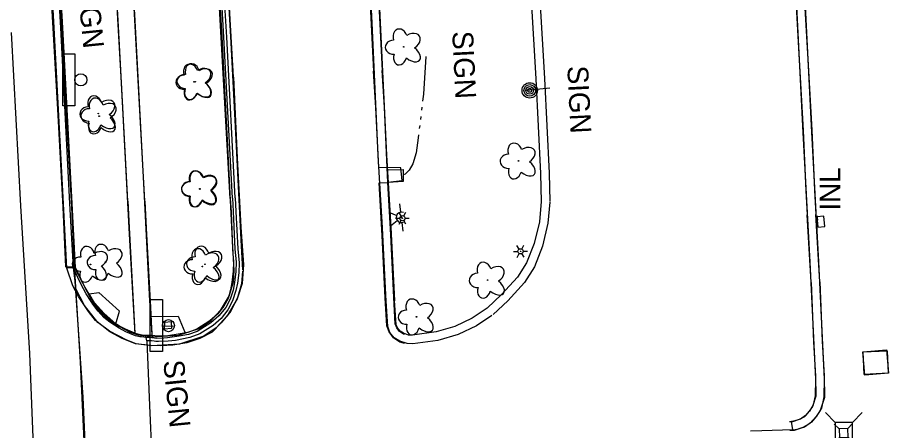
# Model space of a CAD drawing. Extents: x 588843 to 2552415, y 180129 to 269402.
# Drawn here: x 594760.9 to 595012.6, y 184586.7 to 184706 of the extents above; entities that cross this region are included whole.
import ezdxf

# ---------------------------------------------------------------- set-up
doc = ezdxf.new("R2010")
doc.units = 0
for name, color, linetype in [('Default', 7, 'Continuous'), ('E_BLD', 7, 'Continuous'), ('E_DWY', 7, 'Continuous'), ('E_LAND_Vegetation', 7, 'Continuous'), ('E_LTG', 7, 'Continuous'), ('E_MISCPROP', 7, 'Continuous'), ('E_MISCPROP_Planter', 7, 'Continuous'), ('E_PATH_Sidewalk', 7, 'Continuous'), ('E_RDWY', 7, 'Continuous'), ('E_RDWY_AsphConc', 7, 'Continuous'), ('E_RDWY_C_and_G', 7, 'Continuous'), ('E_RDWY_PavtEdge', 7, 'Continuous'), ('E_SGN', 7, 'Continuous'), ('E_SGN_Text', 7, 'Continuous'), ('E_UTL_AG_Bold', 7, 'Continuous'), ('E_WTR_P', 7, 'Continuous'), ('Level 15', 7, 'Continuous'), ('Level 17', 7, 'Continuous'), ('Level 21', 7, 'Continuous')]:
    doc.layers.add(name, color=color, linetype=linetype)

# ---------------------------------------------------------------- blocks, each defined once
blk = doc.blocks.new('SGN_1')
at = {"layer": 'Default'}
blk.add_lwpolyline([(-3.5, -15), (-10.5, -15), (-10.5, 15), (-3.5, 15)], close=True, dxfattribs=at)
blk.add_circle((0, 0), 3.5, dxfattribs=at)
blk = doc.blocks.new('DTRE_1_1')
at = {"layer": 'Default'}
blk.add_circle((-0.18, 0), 0.183, dxfattribs=at)
for centre, major_axis, ratio in [((-1.87, 5.32), (1.36, -4.98), 0.782863), ((4.06, 2.74), (-5.27, -2.93), 0.691916), ((-5.87, 0.15), (4.93, -0.12), 0.832022), ((-2.49, -5.24), (1.8, 4.86), 0.716896), ((3.54, -3.71), (-5.01, 4.58), 0.560249)]:
    blk.add_ellipse(centre, major_axis=major_axis, ratio=ratio, start_param=1.570796, end_param=4.712389, dxfattribs=at)
blk = doc.blocks.new('PED_3')
at = {"layer": 'E_UTL_AG_Bold'}
for p, q in [((-8.2, 8.2), (-17.5, 17.5)), ((8.2, 8.2), (17.5, 17.5)), ((-8.2, -8.2), (-17.5, -17.5)), ((8.2, -8.2), (17.5, -17.5))]:
    blk.add_line(p, q, dxfattribs=at)
blk.add_lwpolyline([(-8.2, -8.2), (8.2, -8.2), (8.2, 8.2), (-8.2, 8.2)], close=True, dxfattribs=at)
blk = doc.blocks.new('LPOL_4')
at = {"layer": 'E_LTG'}
for p, q in [((-13.1, 0), (-4.9, 0)), ((-2.5, 4.3), (-6.6, 11.4)), ((2.5, 4.3), (6.6, 11.4)), ((4.9, 0), (13.1, 0)), ((-6.6, -11.4), (-2.5, -4.3)), ((6.6, -11.4), (2.5, -4.3))]:
    blk.add_line(p, q, dxfattribs=at)
for radius in [4.92, 4.92, 4.92, 0.41]:
    blk.add_circle((0, 0), radius, dxfattribs=at)
blk = doc.blocks.new('SIGN_3')
at = {"layer": 'E_SGN'}
blk.add_text('SIGN', height=39.37, dxfattribs=at).set_placement((-56.1, -19.7))
blk = doc.blocks.new('POLE_3')
at = {"layer": 'E_MISCPROP'}
for radius in [14.6, 11, 7.32, 3.66]:
    blk.add_circle((0, 0), radius, dxfattribs=at)
blk = doc.blocks.new('DTRE_4')
at = {"layer": 'E_LAND_Vegetation'}
blk.add_circle((-0.6, 0), 0.601, dxfattribs=at)
for centre, major_axis, ratio in [((-6.1, 17.5), (4.5, -16.3), 0.782863), ((13.3, 9), (-17.3, -9.6), 0.691916), ((-19.3, 0.5), (16.2, -0.4), 0.832022), ((-8.2, -17.2), (5.9, 15.9), 0.716896), ((11.6, -12.2), (-16.4, 15), 0.560249)]:
    blk.add_ellipse(centre, major_axis=major_axis, ratio=ratio, start_param=1.570796, end_param=4.712389, dxfattribs=at)

msp = doc.modelspace()

# ---------------------------------------------------------------- linework, layer by layer
at = {"layer": 'E_BLD'}
msp.add_lwpolyline([(595005.22, 184609.41), (595012.05, 184610.01), (595012.65, 184603.26), (595005.81, 184602.66)], close=True, dxfattribs=at)
at = {"layer": 'E_DWY'}
for points in [[(594791.51, 184779.58), (594797.65, 184779.85), (594800.87, 184779.39), (594805.25, 184778.25), (594808.67, 184776.58), (594811.56, 184774.69), (594813.89, 184772.2), (594816.89, 184767.41), (594818.56, 184762.99), (594819.34, 184759.34), (594819.97, 184746.98), (594821.08, 184725.47), (594822.5, 184700.4)], [(594823.35, 184688.72), (594822.34, 184707.09), (594821.51, 184721.44), (594820.6, 184737.77), (594819.82, 184751.76), (594819.02, 184762.29), (594817.89, 184766.14), (594816.04, 184769.5), (594814.36, 184771.83), (594812.01, 184774.62), (594809.49, 184776.51), (594807.01, 184777.85), (594804.36, 184779.07), (594801.57, 184779.74), (594799, 184780.2), (594796.53, 184780.25), (594791.54, 184780.11)], [(594867.43, 184624.04), (594866.42, 184645.27), (594865.12, 184666.12), (594863.38, 184704.42), (594861.58, 184740.36), (594860.43, 184765.62), (594859.18, 184779.06)], [(594860.4, 184779.16), (594861.52, 184779.15), (594861.86, 184779.18), (594862.1, 184778.9), (594862.39, 184770.36), (594863.5, 184745.87), (594864.98, 184717.52), (594866.34, 184690.62)], [(594869.93, 184624.16), (594868.92, 184645.4), (594867.62, 184666.25), (594865.87, 184704.54), (594864.08, 184740.48), (594862.93, 184765.79), (594861.65, 184779.57)], [(594791.62, 184777.08), (594797.53, 184777.34), (594800.38, 184776.93), (594804.38, 184775.89), (594807.44, 184774.4), (594809.94, 184772.76), (594811.9, 184770.67), (594814.64, 184766.3), (594816.15, 184762.28), (594816.85, 184759.01), (594817.47, 184746.85), (594818.58, 184725.34), (594820.01, 184700.26)], [(594859.89, 184770.26), (594861.01, 184745.75), (594862.48, 184717.39), (594863.84, 184690.49)], [(594909.4, 184711.15), (594910.76, 184688.21), (594912.06, 184660.91), (594912.29, 184652.75)], [(594911.89, 184711.29), (594913.26, 184688.34), (594914.56, 184661), (594914.78, 184652.82)], [(594985.94, 184711.17), (594987.84, 184672.73), (594989.92, 184635.28), (594991.5, 184601.52), (594991.47, 184596.74), (594990.88, 184594.12), (594989.82, 184592.32), (594988.34, 184590.7), (594986.83, 184589.87), (594984.9, 184589.22), (594984, 184589.19)], [(594988.43, 184711.29), (594990.34, 184672.86), (594992.42, 184635.4), (594994, 184601.57), (594993.97, 184596.46), (594993.24, 184593.19), (594991.84, 184590.82), (594989.91, 184588.71), (594987.84, 184587.57), (594985.35, 184586.74), (594984.11, 184586.69)], [(594820, 184700.38), (594821.46, 184672.4), (594823.08, 184639.78), (594823.47, 184632.92)], [(594822.5, 184700.51), (594823.95, 184672.53), (594825.57, 184639.92), (594825.96, 184633.06)], [(594865.31, 184662.52), (594864.45, 184679.93), (594863.84, 184690.49)], [(594867.8, 184662.64), (594866.95, 184680.07), (594866.34, 184690.62)], [(594823.35, 184688.72), (594824.43, 184665.41), (594825.5, 184645.45), (594826.2, 184634.6), (594825.88, 184629.16), (594824.62, 184625.26), (594822.61, 184621.18), (594819.74, 184617.79), (594817.17, 184615.12), (594813.67, 184613.24), (594809.86, 184612.06), (594805.78, 184611.37), (594802.31, 184611.16), (594799.42, 184611.26), (594795.05, 184611.7), (594791.14, 184613.24), (594787.65, 184615.21), (594783.48, 184618.49), (594781.43, 184621.03), (594778.6, 184625.44), (594776.95, 184628.49), (594775.2, 184633.55)], [(594865.46, 184658.21), (594867.95, 184658.36), (594867.8, 184662.64), (594865.31, 184662.52)], [(594872.79, 184611.81), (594871.42, 184612.23), (594869.55, 184613.45), (594868.37, 184615.19), (594867.63, 184616.94), (594867.18, 184625.01), (594866.35, 184643.06), (594865.46, 184658.21)], [(594872.77, 184614.43), (594872.49, 184614.52), (594871.34, 184615.27), (594870.57, 184616.39), (594870.1, 184617.51), (594869.68, 184625.14), (594868.85, 184643.19), (594867.95, 184658.36)], [(594912.28, 184652.87), (594911.76, 184646.97), (594910.28, 184640.73), (594908.06, 184635.12), (594905.43, 184630.96), (594900.82, 184625.93), (594896.63, 184622.01)], [(594914.77, 184652.65), (594914.23, 184646.57), (594912.67, 184639.98), (594910.3, 184633.99), (594907.43, 184629.44), (594902.6, 184624.17), (594898.34, 184620.19)], [(594823.47, 184632.92), (594823.21, 184629.51), (594822.13, 184625.72), (594819.54, 184621.34), (594816.71, 184618.26), (594813.66, 184616.17), (594807.33, 184614.09), (594799.74, 184613.7), (594795.79, 184614.21), (594793.58, 184615.05), (594788.86, 184617.53), (594785.9, 184619.71), (594782.37, 184624.2), (594777.31, 184634.09)], [(594825.96, 184632.73), (594825.68, 184629.07), (594824.44, 184624.73), (594821.56, 184619.85), (594818.36, 184616.36), (594814.78, 184613.9), (594807.79, 184611.61), (594799.64, 184611.19), (594795.18, 184611.77), (594792.55, 184612.77), (594787.53, 184615.4), (594784.14, 184617.9), (594780.26, 184622.84), (594777.72, 184627.81)], [(594898.01, 184619.93), (594893.56, 184616.97), (594888.24, 184614.44), (594882.39, 184612.73), (594875.21, 184611.76), (594873.49, 184611.78), (594871.37, 184612.53), (594869.82, 184613.47), (594868.54, 184615.05), (594867.91, 184616.7), (594867.43, 184624.07)], [(594896.63, 184622.01), (594892.33, 184619.15), (594887.35, 184616.78), (594881.87, 184615.18), (594875.06, 184614.26), (594873.94, 184614.27), (594872.45, 184614.8), (594871.49, 184615.38), (594870.73, 184616.32), (594870.38, 184617.24), (594869.92, 184624.23)]]:
    msp.add_lwpolyline(points, dxfattribs=at)
at = {"layer": 'E_LTG'}
for p, q in [((594868.21, 184649.79), (594870.51, 184648.81)), ((594871.71, 184649.72), (594871.41, 184652.2)), ((594868.69, 184645.82), (594870.69, 184647.33)), ((594872.37, 184644.26), (594872.07, 184646.74))]:
    msp.add_line(p, q, dxfattribs=at)
msp.add_circle((594871.89, 184648.23), 0.125, dxfattribs=at)
msp.add_arc((594871.89, 184648.23), 1.5, 68.7097, 292.3879, dxfattribs=at)
at = {"layer": 'E_MISCPROP_Planter'}
msp.add_lwpolyline([(594799.67, 184619.64), (594807.33, 184619.74), (594809.32, 184615.14)], dxfattribs=at)
at = {"layer": 'E_PATH_Sidewalk'}
for points in [[(594797.74, 184652.91), (594794.94, 184703.55), (594793.4, 184731.28), (594796.14, 184735.68), (594795.81, 184750.1), (594792.41, 184753.56), (594791.37, 184777.06), (594786.45, 184776.63)], [(594792.8, 184652.96), (594790.08, 184703.35), (594788.47, 184732.25), (594791.3, 184737.24), (594790.98, 184748.34), (594787.5, 184752.99), (594786.45, 184776.63)], [(594791.25, 184776.72), (594786.56, 184776.42), (594787.4, 184753.25), (594787.66, 184752.35), (594790.93, 184748.04), (594791.31, 184736.87), (594788.45, 184731.85), (594788.53, 184729.27), (594790.77, 184688.8), (594793.22, 184643.35), (594794.8, 184614.59)], [(594791.18, 184776.71), (594792.42, 184753.24), (594795.34, 184750.57), (594795.67, 184749.96), (594796.29, 184736.37), (594796.13, 184735.8), (594793.18, 184731.22), (594794.7, 184706.82), (594797.33, 184658.05), (594799.1, 184624.16), (594799.83, 184613.6)], [(594792.8, 184652.96), (594793.24, 184645.36), (594794.5, 184622.01), (594794.8, 184614.83)], [(594797.74, 184652.91), (594798.07, 184645.09), (594799.35, 184622.2), (594799.72, 184614.11)]]:
    msp.add_lwpolyline(points, dxfattribs=at)
at = {"layer": 'E_RDWY'}
for points in [[(594867.95, 184658.46), (594872.12, 184658.89), (594871.75, 184662.52), (594867.81, 184662.6)], [(594867.78, 184661.98), (594872.36, 184662.06), (594872.41, 184658.61), (594868.01, 184658.33)], [(594777.4, 184632.83), (594779.06, 184606.45), (594780.67, 184571.28), (594781.19, 184555.56), (594782.21, 184523.33), (594782.74, 184513.75), (594784.36, 184495.78), (594784.28, 184494.37)]]:
    msp.add_lwpolyline(points, dxfattribs=at)
at = {"layer": 'E_RDWY_AsphConc'}
for points in [[(594781.64, 184555.76), (594781.37, 184563.82), (594779.87, 184596.3), (594777.6, 184629.78), (594777.08, 184633.63)], [(594789.34, 184617.54), (594785.96, 184620.52), (594783.2, 184623.61), (594781.65, 184626.13), (594784.42, 184626.52), (594790.45, 184621.12)], [(594789.34, 184617.54), (594790.45, 184621.12)], [(594798.34, 184612.59), (594799.04, 184593.94), (594799.76, 184578.72), (594799.79, 184578.23)]]:
    msp.add_lwpolyline(points, dxfattribs=at)
msp.add_lwpolyline([(594805.42, 184616.19), (594803.46, 184616), (594803.48, 184618.03), (594805.36, 184618.17)], close=True, dxfattribs=at)
at = {"layer": 'E_RDWY_C_and_G'}
for points in [[(594764.27, 184831.13), (594766.46, 184789.1), (594769.36, 184734.71), (594772.55, 184677.72)], [(594766.76, 184831.26), (594768.96, 184789.23), (594771.86, 184734.85), (594775.04, 184677.86)], [(594777.08, 184633.63), (594775.2, 184633.55), (594774.21, 184652.19), (594771.49, 184702.97), (594768.71, 184753.45), (594765.95, 184803.81)], [(594778.76, 184630.05), (594777.08, 184633.63), (594776.1, 184652.26), (594773.41, 184702.94), (594770.48, 184753.24), (594767.8, 184803.8)], [(594779.34, 184630.27), (594777.65, 184633.73), (594776.77, 184652.29), (594773.99, 184703.02), (594771.16, 184753.32), (594768.38, 184803.92)], [(594822.37, 184653.72), (594819.8, 184700.18), (594818.89, 184715.65)], [(594823.06, 184653.8), (594820.55, 184700.24), (594819.67, 184715.66)], [(594823.84, 184653.88), (594821.39, 184700.32), (594820.5, 184715.79)], [(594772.55, 184677.72), (594774, 184651.16), (594774.81, 184633.97), (594777.31, 184634.09)], [(594775.04, 184677.86), (594776.5, 184651.29), (594777.31, 184634.09)], [(594823.06, 184653.8), (594823.24, 184649.94), (594823.76, 184639.07), (594824.13, 184635.38), (594824.13, 184635.38), (594824.07, 184632.64), (594824.07, 184632.64), (594823.68, 184629.43), (594823.68, 184629.43), (594823.25, 184627.18), (594823.25, 184627.18), (594822.41, 184624.61), (594821.09, 184622.25), (594821.09, 184622.25), (594819.13, 184619.86), (594816.8, 184617.83), (594816.8, 184617.83), (594812.83, 184615.34), (594812.83, 184615.34), (594810.37, 184614.44), (594810.37, 184614.44), (594807.68, 184613.93), (594807.68, 184613.93), (594804.27, 184613.45), (594804.27, 184613.45), (594803.18, 184613.35), (594803.18, 184613.35), (594801.18, 184613.28), (594801.18, 184613.28), (594799.75, 184613.51), (594798.16, 184613.59), (594796.76, 184613.73), (594796.31, 184613.78), (594795.05, 184614.05), (594795.05, 184614.05), (594794.56, 184614.21), (594794.56, 184614.21), (594792.21, 184615.22), (594792.21, 184615.22), (594790.27, 184616.22), (594790.27, 184616.22), (594787.59, 184617.94), (594787.59, 184617.94), (594785.92, 184619.34), (594785.92, 184619.34), (594784.23, 184621.19), (594784.23, 184621.19), (594782.7, 184623.22), (594782.7, 184623.22), (594782.21, 184623.97), (594782.21, 184623.97), (594780.77, 184626.21), (594780.77, 184626.21), (594779.96, 184627.62), (594779.96, 184627.62), (594778.76, 184630.05), (594778.76, 184630.05)], [(594822.37, 184653.72), (594822.67, 184649.81), (594823.1, 184639.09), (594823.38, 184635.41), (594823.38, 184635.41), (594823.29, 184632.67), (594823.29, 184632.67), (594822.91, 184629.46), (594822.91, 184629.46), (594822.53, 184627.29), (594822.53, 184627.29), (594821.77, 184624.85), (594820.55, 184622.59), (594820.55, 184622.59), (594818.73, 184620.31), (594816.55, 184618.37), (594816.55, 184618.37), (594812.71, 184615.95), (594812.71, 184615.95), (594810.13, 184615.01), (594810.13, 184615.01), (594807.4, 184614.49), (594807.4, 184614.49), (594804.34, 184614.06), (594804.34, 184614.06), (594803.38, 184613.99), (594803.38, 184613.99), (594801.58, 184613.95), (594801.58, 184613.95), (594799.72, 184614.11), (594798.2, 184614.15), (594796.97, 184614.19), (594796.52, 184614.34), (594795.3, 184614.66), (594795.3, 184614.66), (594794.8, 184614.83), (594794.8, 184614.83), (594792.12, 184615.96), (594792.12, 184615.96), (594790.43, 184616.82), (594790.43, 184616.82), (594788.38, 184618.13), (594788.38, 184618.13), (594786.38, 184619.78), (594786.38, 184619.78), (594784.27, 184621.95), (594784.27, 184621.95), (594783.09, 184623.55), (594783.09, 184623.55), (594782.72, 184624.15), (594782.72, 184624.15), (594781.33, 184626.52), (594781.33, 184626.52), (594780.53, 184627.96), (594780.53, 184627.96), (594779.34, 184630.27), (594779.34, 184630.27)], [(594823.84, 184653.88), (594824.03, 184649.92), (594824.65, 184639.12), (594825.01, 184635.15), (594825.01, 184635.15), (594824.89, 184632.19), (594824.89, 184632.19), (594824.47, 184629.29), (594824.47, 184629.29), (594824.04, 184627.09), (594824.04, 184627.09), (594823.1, 184624.19), (594821.67, 184621.51), (594821.67, 184621.51), (594819.78, 184619.09), (594817.49, 184617.05), (594817.49, 184617.05), (594813.61, 184614.61), (594813.61, 184614.61), (594810.72, 184613.55), (594810.72, 184613.55), (594806.6, 184612.72), (594806.6, 184612.72), (594804.43, 184612.48), (594804.43, 184612.48), (594801.65, 184612.38), (594801.65, 184612.38), (594800.93, 184612.41), (594800.93, 184612.41), (594800.41, 184612.46), (594800.41, 184612.46), (594799.62, 184612.56), (594799.62, 184612.56), (594799.16, 184612.59), (594799.16, 184612.59), (594798.34, 184612.59), (594798.34, 184612.59), (594798.16, 184613.59)]]:
    msp.add_lwpolyline(points, dxfattribs=at)
at = {"layer": 'E_RDWY_PavtEdge'}
msp.add_lwpolyline([(594769.3, 184449.63), (594768.81, 184476.19), (594768.17, 184495.11), (594766.41, 184560.33), (594764.46, 184608.96), (594761.88, 184651.59), (594759.18, 184701.67)], dxfattribs=at)
at = {"layer": 'E_SGN'}
for p, q in [((594908.04, 184684.97), (594914.8, 184685.69)), ((594803.1, 184616.95), (594805.94, 184616.86))]:
    msp.add_line(p, q, dxfattribs=at)
at = {"layer": 'E_WTR_P'}
for points in [[(594878.9, 184694.71), (594878.23, 184683.78), (594878, 184681.83)], [(594877.79, 184680.06), (594877.68, 184679.18)], [(594877.47, 184677.41), (594877.36, 184676.52)], [(594877.15, 184674.76), (594877.04, 184673.87)], [(594876.82, 184672.11), (594876.71, 184671.25), (594876.1, 184666.9), (594875.19, 184663.72), (594874.14, 184661.84), (594873, 184660.68), (594872.45, 184660.55)]]:
    msp.add_lwpolyline(points, dxfattribs=at)
at = {"layer": 'Level 15'}
msp.add_lwpolyline([(594992.25, 184645.39), (594994.23, 184645.61), (594993.9, 184648.59), (594991.91, 184648.37), (594992.25, 184645.39)], dxfattribs=at)
at = {"layer": 'Level 17'}
for points in [[(594985.81, 184711.02), (594986.83, 184693.76), (594987.94, 184673.3), (594988.74, 184655.93), (594989.15, 184649.05)], [(594988.36, 184710.27), (594989.33, 184693.9), (594990.43, 184673.43), (594991.24, 184656.06), (594991.66, 184649.05)], [(594990.27, 184629.5), (594989.15, 184649.02)], [(594992.77, 184629.63), (594991.65, 184649.09)], [(594991.66, 184649.05), (594991.66, 184649.02)], [(594992.02, 184648.66), (594992.05, 184648.18), (594992.09, 184647.4), (594991.75, 184647.38)], [(594992.77, 184629.63), (594993.42, 184612.48), (594994.07, 184602.47), (594994.13, 184596.25), (594992.91, 184592.46), (594991.7, 184590.79), (594990.34, 184589.16), (594988.31, 184587.7), (594985.81, 184586.94)], [(594990.27, 184629.48), (594990.92, 184612.35), (594991.57, 184602.38), (594991.63, 184596.63), (594990.66, 184593.61), (594989.73, 184592.32), (594988.63, 184591.01), (594987.19, 184589.97), (594985.17, 184589.36), (594984.64, 184589.29)], [(594984.94, 184586.91), (594976.02, 184586.59), (594972.73, 184586.48)], [(594984.94, 184586.91), (594984.64, 184589.29)], [(594985.81, 184586.94), (594985.7, 184586.9), (594984.96, 184586.81), (594984.94, 184586.91)]]:
    msp.add_lwpolyline(points, dxfattribs=at)
at = {"layer": 'Level 21'}
for p, q in [((594997.22, 184589.05), (594994.39, 184591.88)), ((595002.22, 184589.05), (595005.05, 184591.88))]:
    msp.add_line(p, q, dxfattribs=at)
msp.add_lwpolyline([(595005.6, 184602.86), (595005.27, 184609.39), (595012.21, 184609.74), (595012.54, 184603.22), (595005.6, 184602.86)], dxfattribs=at)
msp.add_lwpolyline([(594997.22, 184584.05), (595002.22, 184584.05), (595002.22, 184589.05), (594997.22, 184589.05)], close=True, dxfattribs=at)

# ---------------------------------------------------------------- block references
at = {"layer": 'E_LAND_Vegetation', "xscale": 0.15240030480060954, "yscale": 0.15240030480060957, "rotation": 3.4338469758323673}
for p in [(594872.63, 184697.5), (594812.09, 184687.38), (594784.38, 184678.21), (594905.8, 184664.56), (594813.7, 184656.51), (594786.45, 184635.33), (594814.45, 184634.08), (594896.88, 184630.15), (594876.33, 184619.54)]:
    msp.add_blockref('DTRE_4', p, dxfattribs=at)
at = {"layer": 'E_LAND_Vegetation', "xscale": 0.5, "yscale": 0.5}
for p in [(594812.41, 184687.41), (594784.63, 184677.47), (594813.71, 184656.43), (594782.12, 184634.66), (594815.18, 184634.71)]:
    msp.add_blockref('DTRE_1_1', p, dxfattribs=at)
at = {"layer": 'E_LTG', "xscale": 0.15240030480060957, "yscale": 0.15240030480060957, "rotation": 0.8014450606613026}
for p in [(594872.16, 184648), (594906.29, 184638.44)]:
    msp.add_blockref('LPOL_4', p, dxfattribs=at)
at = {"layer": 'E_MISCPROP', "xscale": 0.15240030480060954, "yscale": 0.15240030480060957, "rotation": 3.4338469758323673}
msp.add_blockref('POLE_3', (594908.95, 184684.91), dxfattribs=at)
at = {"layer": 'E_SGN', "xscale": 0.5, "yscale": 0.5}
for p in [(594779.25, 184687.98), (594804.54, 184616.99)]:
    msp.add_blockref('SGN_1', p, dxfattribs=at)
at = {"layer": 'E_SGN_Text', "xscale": 0.15240030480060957}
for p, yscale, rotation in [((594781.91, 184708.09), 0.1524003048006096, -84.31519139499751), ((594889.97, 184693.52), 0.15240030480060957, -87.12209734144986), ((594923.22, 184683.52), 0.15240030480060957, -87.12209734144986), ((594806.87, 184598.57), 0.1524003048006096, -84.31519139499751)]:
    msp.add_blockref('SIGN_3', p, dxfattribs=dict(at, yscale=yscale, rotation=rotation))
at = {"layer": 'E_UTL_AG_Bold', "xscale": 0.1524003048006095, "yscale": 0.15240030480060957, "rotation": 2.3276622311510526}
msp.add_blockref('PED_3', (594999.69, 184585.97), dxfattribs=at)

# ---------------------------------------------------------------- texts
at = {"layer": 'Level 15'}
msp.add_text('INL', height=6, rotation=90, dxfattribs=at).set_placement((594998.74, 184650.2))

doc.saveas('drawing.dxf')
